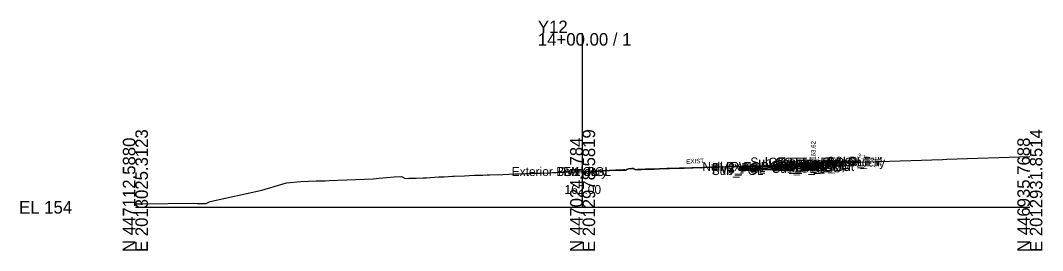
# Model space of a CAD drawing. Extents: x -26 to 1203, y -10 to 9542.
# Drawn here: x -25.7 to 202.8, y 7990.3 to 8041.9 of the extents above; entities that cross this region are included whole.
import ezdxf

# ---------------------------------------------------------------- set-up
doc = ezdxf.new("R2010")
doc.units = 0
for name, color, linetype in [('Default', 7, 'Continuous'), ('Exist Cross Section Cell', 7, 'Continuous'), ('Exist XS Center Line Elevation Label', 7, 'Continuous'), ('Exist XS Ground Line', 7, 'Continuous'), ('Prop CMT Conc Surface', 7, 'Continuous'), ('Prop CMT Concrete Structures', 7, 'Continuous'), ('Prop CMT Pvmt Course 1', 7, 'Continuous'), ('Prop CMT Pvmt Course 1 CG', 7, 'Continuous'), ('Prop CMT Pvmt Course 2', 7, 'Continuous'), ('Prop CMT Pvmt Course 3', 7, 'Continuous'), ('Prop CMT Pvmt Surface', 7, 'Continuous'), ('Prop CMT Slope Grass', 7, 'Continuous'), ('Prop CMT Subgrade Earthwork', 7, 'Continuous'), ('Prop XS Earthwork Shape', 7, 'Continuous'), ('Prop XS Hydro Elevations', 7, 'Continuous'), ('Prop XS SE Text', 7, 'Continuous'), ('Prop XS Side Slope Text', 7, 'Continuous'), ('Scratch_Level_0', 7, 'Continuous')]:
    doc.layers.add(name, color=color, linetype=linetype)

msp = doc.modelspace()

# ---------------------------------------------------------------- linework, layer by layer
at = {"layer": 'Exist Cross Section Cell'}
for p, q in [((100, 8000), (100, 8039.01)), ((0, 8000), (100, 8000)), ((100, 8000), (200, 8000))]:
    msp.add_line(p, q, dxfattribs=at)
at = {"layer": 'Exist XS Ground Line'}
msp.add_lwpolyline([(0, 8000.78), (0.54, 8000.78), (0.9, 8000.78), (1.25, 8000.78), (1.58, 8000.78), (13.09, 8000.9), (13.91, 8000.88), (15.83, 8000.82), (16.75, 8001.32), (28.27, 8003.86), (33.83, 8005.47), (36.99, 8005.81), (40.44, 8005.9), (40.78, 8005.9), (41.25, 8005.91), (41.83, 8005.93), (42.45, 8005.96), (43.34, 8006.01), (53.2, 8006.41), (54.48, 8006.53), (56.13, 8006.67), (57.89, 8006.8), (59.5, 8006.9), (60.33, 8006.46), (61.18, 8006.5), (62.33, 8006.55), (62.77, 8006.55), (64.38, 8006.59), (65.06, 8006.61), (65.89, 8006.66), (67.89, 8006.81), (69.03, 8006.86), (70.93, 8006.95), (71.28, 8006.97), (73.56, 8007.07), (74.6, 8007.12), (75.8, 8007.16), (76.37, 8007.17), (77.72, 8007.18), (78.69, 8007.25), (79.23, 8007.27), (82.17, 8007.38), (84.88, 8007.46), (85.72, 8007.49), (87.3, 8007.54), (87.7, 8007.56), (88.28, 8007.58), (89.03, 8007.62), (90.51, 8007.67), (92.62, 8007.75), (93.32, 8007.78), (94.1, 8007.8), (96.15, 8007.88), (97.98, 8007.94), (98.77, 8007.96), (99.08, 8007.97), (100, 8008), (100.48, 8008.02), (101.81, 8008.07), (102.34, 8008.09), (103.32, 8008.13), (104.63, 8008.18), (106.03, 8008.23), (107.44, 8008.28), (108.31, 8008.32), (109.69, 8008.35), (110.29, 8008.65), (110.97, 8008.69), (111.28, 8008.69), (111.88, 8008.39), (112.42, 8008.48), (113.19, 8008.5), (114.05, 8008.52), (115.31, 8008.55), (115.98, 8008.57), (117.17, 8008.61), (118.81, 8008.66), (119.41, 8008.68), (121.65, 8008.77), (122.74, 8008.8), (124.44, 8008.85), (124.74, 8008.86), (127.25, 8008.94), (130.1, 8009.02), (131.93, 8009.08), (132.9, 8009.1), (133.95, 8009.13), (135.05, 8009.15), (135.84, 8009.15), (136.65, 8009.15), (137.92, 8009.31), (138.63, 8009.22), (139.41, 8009.24), (141.66, 8009.35), (143.98, 8009.47), (144.43, 8009.49), (145.19, 8009.53), (145.92, 8009.57), (150.09, 8009.79), (160.65, 8010.1), (163.9, 8010.2), (180.5, 8010.72), (181.4, 8010.75), (200, 8011.34)], dxfattribs=at)
at = {"layer": 'Prop CMT Conc Surface'}
msp.add_lwpolyline([(149.6, 8009.63), (151.6, 8009.62), (151.6, 8010.12), (152.1, 8010.12)], dxfattribs=at)
at = {"layer": 'Prop CMT Concrete Structures'}
for points in [[(149.6, 8009.63), (151.6, 8009.62), (151.6, 8010.12), (152.1, 8010.12)], [(152.1, 8010.12), (152.1, 8009.13), (149.6, 8009.05)], [(149.6, 8009.05), (149.6, 8009.63)]]:
    msp.add_lwpolyline(points, dxfattribs=at)
at = {"layer": 'Prop CMT Pvmt Course 1'}
for points in [[(135.05, 8009.15), (133.95, 8009.13), (132.9, 8009.1), (131.93, 8009.08), (130.1, 8009.02), (130.05, 8009.02), (127.25, 8008.94), (124.74, 8008.86), (124.44, 8008.85), (122.75, 8008.8), (122.74, 8008.8), (122.7, 8008.8), (121.65, 8008.77), (119.41, 8008.68), (118.81, 8008.66), (117.17, 8008.61), (115.98, 8008.57), (115.31, 8008.55), (114.05, 8008.52), (113.19, 8008.5), (112.42, 8008.48), (112.24, 8008.45), (111.88, 8008.39), (111.71, 8008.47), (111.28, 8008.69), (110.97, 8008.69), (110.29, 8008.65), (109.86, 8008.44), (109.69, 8008.35), (109.43, 8008.36), (109.29, 8008.37), (109.18, 8008.36), (108.31, 8008.32), (107.44, 8008.28), (106.03, 8008.23), (104.63, 8008.18), (103.32, 8008.13), (102.34, 8008.09), (101.81, 8008.07), (100.48, 8008.02), (100, 8008)], [(100, 8008), (100, 8008)], [(135.05, 8009.15), (149.6, 8009.63)], [(149.6, 8009.38), (135.05, 8008.9)], [(135.05, 8009.15), (135.05, 8009.15)], [(135.05, 8008.9), (135.05, 8009.15)], [(149.6, 8009.63), (149.6, 8009.38)]]:
    msp.add_lwpolyline(points, dxfattribs=at)
at = {"layer": 'Prop CMT Pvmt Course 1 CG'}
for points in [[(149.6, 8009.05), (152.6, 8009.15), (152.92, 8008.82)], [(149.6, 8008.71), (149.6, 8009.05)], [(152.92, 8008.82), (149.6, 8008.71)]]:
    msp.add_lwpolyline(points, dxfattribs=at)
at = {"layer": 'Prop CMT Pvmt Course 2'}
for points in [[(135.05, 8008.9), (149.6, 8009.38)], [(149.6, 8009.05), (135.05, 8008.57)], [(135.05, 8008.57), (135.05, 8008.9)], [(149.6, 8009.38), (149.6, 8009.05)]]:
    msp.add_lwpolyline(points, dxfattribs=at)
at = {"layer": 'Prop CMT Pvmt Course 3'}
for points in [[(135.05, 8008.57), (149.6, 8009.05)], [(149.6, 8008.71), (135.05, 8008.24)], [(135.05, 8008.24), (135.05, 8008.57)], [(149.6, 8009.05), (149.6, 8008.71)]]:
    msp.add_lwpolyline(points, dxfattribs=at)
at = {"layer": 'Prop CMT Pvmt Surface'}
msp.add_lwpolyline([(135.05, 8009.15), (149.6, 8009.63)], dxfattribs=at)
at = {"layer": 'Prop CMT Slope Grass'}
msp.add_lwpolyline([(152.1, 8010.12), (161.6, 8010.31), (162.09, 8010.14)], dxfattribs=at)
at = {"layer": 'Prop CMT Subgrade Earthwork'}
for points in [[(149.6, 8008.71), (152.92, 8008.82), (154.25, 8010.16)], [(135.05, 8008.24), (135.05, 8009.15)], [(135.05, 8008.24), (149.6, 8008.71)], [(149.6, 8008.71), (135.05, 8008.24)]]:
    msp.add_lwpolyline(points, dxfattribs=at)
at = {"layer": 'Prop XS Earthwork Shape'}
for points in [[(154, 8009.91), (160.65, 8010.1), (162.09, 8010.14), (161.6, 8010.31), (154.25, 8010.16)], [(149.6, 8008.71), (152.92, 8008.82), (154, 8009.91), (152.1, 8009.85), (152.1, 8009.13), (149.6, 8009.05), (149.6, 8009.63), (142.92, 8009.41), (141.66, 8009.35), (139.41, 8009.24), (138.63, 8009.22), (138.29, 8009.26), (137.3, 8009.23), (136.65, 8009.15), (135.84, 8009.15), (135.05, 8009.15), (135.05, 8008.24)], [(137.92, 8009.31), (138.29, 8009.26), (137.3, 8009.23)], [(149.6, 8009.63), (151.6, 8009.62), (151.6, 8009.84), (150.09, 8009.79), (145.92, 8009.57), (145.19, 8009.53), (144.43, 8009.49), (143.98, 8009.47), (142.92, 8009.41)], [(149.6, 8009.63), (151.6, 8009.62), (151.6, 8009.84), (152.1, 8009.85), (152.1, 8009.13), (149.6, 8009.05)]]:
    msp.add_lwpolyline(points, close=True, dxfattribs=at)

# ---------------------------------------------------------------- texts
at = {"layer": 'Default'}
msp.add_text('-', height=0.0001, dxfattribs=at).set_placement((0, 8000))
at = {"layer": 'Exist Cross Section Cell'}
for s, p in [('Y12', (90, 8039.01)), ('14+00.00 / 1', (90, 8036.21)), ('EL 154', (-26, 7998.6))]:
    msp.add_text(s, height=2.8, dxfattribs=at).set_placement(p)
for s, p in [('E 2013025.3123', (2.8, 7990)), ('E 2012978.5819', (102.8, 7990)), ('E 2012931.8514', (202.8, 7990)), ('N 447112.5880', (0, 7990)), ('N 447024.1784', (100, 7990)), ('N 446935.7688', (200, 7990))]:
    msp.add_text(s, height=2.8, rotation=90, dxfattribs=at).set_placement(p)
at = {"layer": 'Exist XS Center Line Elevation Label'}
msp.add_text('162.00', height=2, dxfattribs=at).set_placement((95.95, 8003))
at = {"layer": 'Prop XS Hydro Elevations'}
msp.add_text('163.62', height=1, rotation=90, dxfattribs=at).set_placement((152.1, 8010.62))
at = {"layer": 'Prop XS SE Text'}
msp.add_text('EXIST', height=1, rotation=1.8799, dxfattribs=at).set_placement((123.19, 8009.77))
at = {"layer": 'Prop XS Side Slope Text'}
msp.add_text('3:1', height=1, rotation=341.5651, dxfattribs=at).set_placement((161.33, 8011.19))
at = {"layer": 'Scratch_Level_0'}
for s, p in [('Null Ex EOP', (126.75, 8008.15)), ('PV1', (133.13, 8008.15)), ('Sub_Trench_Out_DLT', (137.51, 8009.16)), ('CG_Top_Face', (141.55, 8009.12)), ('CG1_Shelf_Out', (141.84, 8008.15)), ('CG_Bot_IE', (142.2, 8008.05)), ('CG_Top_Gut', (142.52, 8008.62)), ('PV2_OEOT', (142.46, 8008.38)), ('PV3_OEOT', (142.46, 8008.05)), ('CG_Top_BOC', (143.07, 8009.12)), ('CG_Bot_BOC', (143.1, 8008.13)), ('PV1_OEOT', (143.03, 8008.63)), ('Exterior Boundary', (146.23, 8009.14)), ('CSLP_Pnt', (154.46, 8009.31)), ('Slope_Fill', (155.31, 8009.14)), ('Exterior Boundary', (84.14, 8007)), ('PV1_PGL', (94.47, 8007)), ('EX CL', (95.67, 8007)), ('Sub_PGL', (128.86, 8007.24)), ('PV2_PGL', (128.96, 8007.9)), ('PV3_PGL', (128.96, 8007.57)), ('Sub_OEOT', (142.37, 8007.71)), ('Sub_OEOP', (145.72, 8007.82))]:
    msp.add_text(s, height=2, dxfattribs=at).set_placement(p)

doc.saveas('drawing.dxf')
